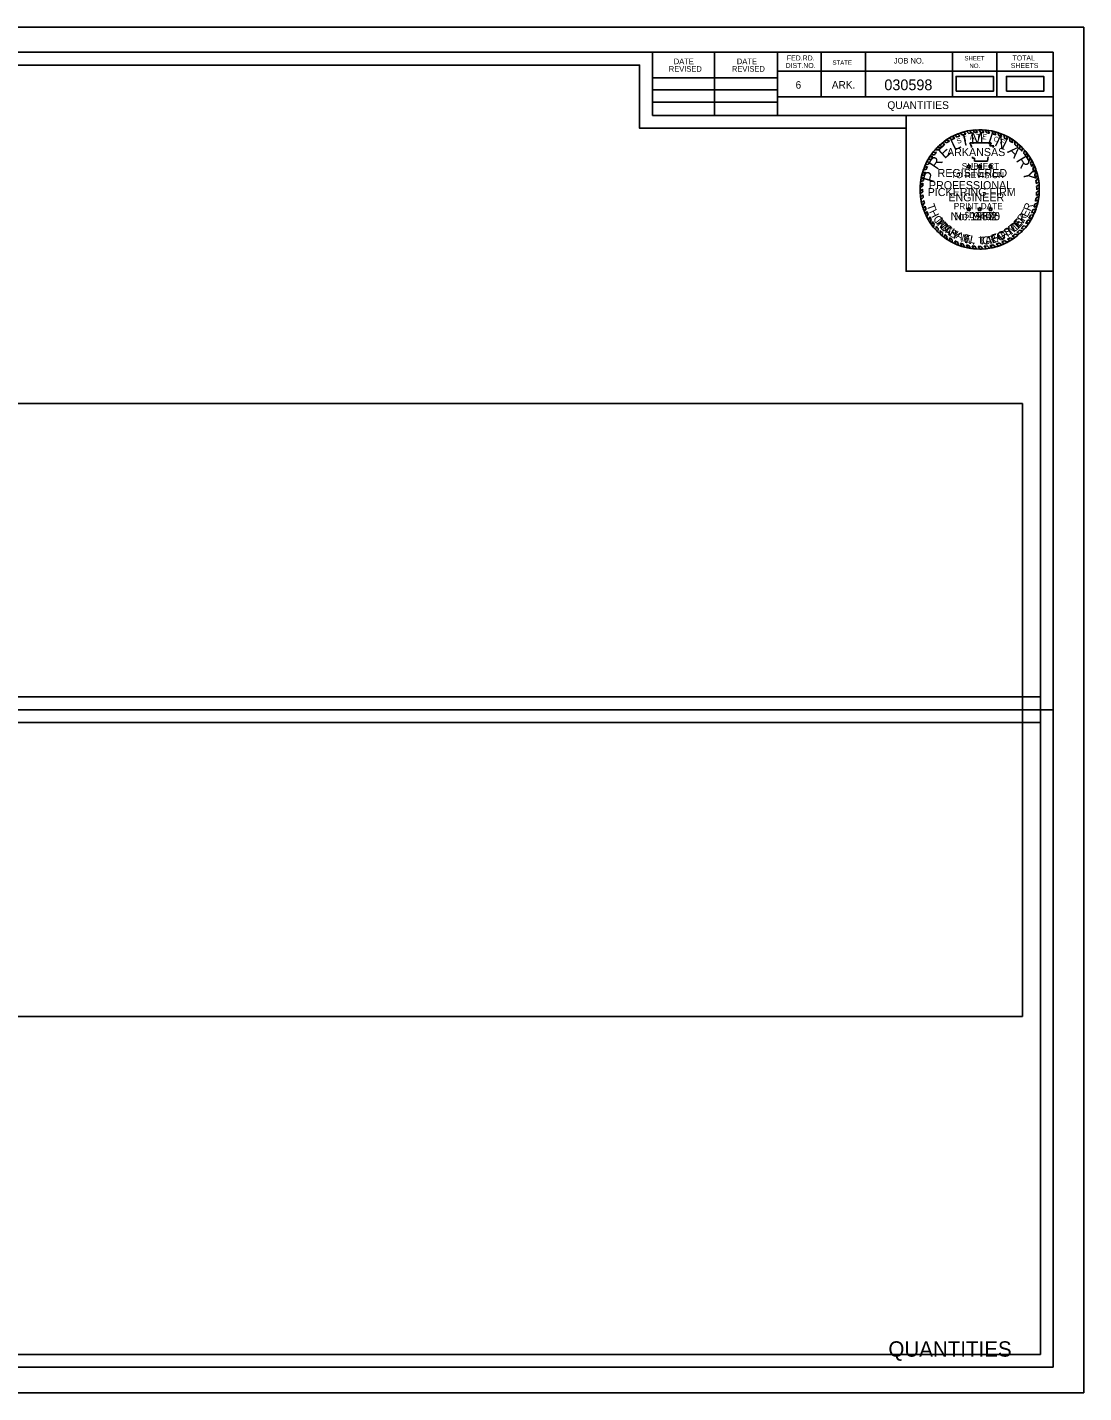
# Model space of a CAD drawing. Extents: x 1369904 to 1372237, y 380119 to 380332.
# Drawn here: x 1371571.9 to 1371736.9, y 380119.1 to 380332.4 of the extents above; entities that cross this region are included whole.
import ezdxf

# ---------------------------------------------------------------- set-up
doc = ezdxf.new("R2010")
doc.units = 0
for name, color, linetype in [('Default', 7, 'Continuous'), ('R_Border', 7, 'Continuous'), ('R_Border Notes', 7, 'Continuous'), ('R_Border Plan-Plan', 7, 'Continuous'), ('R_Border Title', 7, 'Continuous'), ('R_No Plot', 7, 'Continuous'), ('STAMP_PE_CRAFTON', 7, 'Continuous'), ('STAMP_PE_FOSTER', 7, 'Continuous'), ('STAMP_PE_SEAL-INFO', 7, 'Continuous'), ('STAMP_PE_TAEGTMEYER', 7, 'Continuous'), ('STAMP_PE_TXT', 7, 'Continuous'), ('STAMP_PRELIMINARY', 7, 'Continuous')]:
    doc.layers.add(name, color=color, linetype=linetype)

msp = doc.modelspace()

# ---------------------------------------------------------------- linework, layer by layer
at = {"layer": 'Default'}
for points in [[(1371717, 380322.41), (1371722.83, 380322.41), (1371722.83, 380324.72), (1371717, 380324.72)], [(1371724.87, 380322.41), (1371730.7, 380322.41), (1371730.7, 380324.72), (1371724.87, 380324.72)], [(1371420.25, 380177.85), (1371727.35, 380177.85), (1371727.35, 380273.61), (1371420.25, 380273.61)]]:
    msp.add_lwpolyline(points, close=True, dxfattribs=at)
at = {"layer": 'R_Border'}
for p, q in [((1371416, 380328.5), (1371732.18, 380328.5)), ((1371669.54, 380318.62), (1371669.54, 380328.5)), ((1371679.22, 380318.62), (1371679.22, 380328.5)), ((1371689.08, 380328.5), (1371689.08, 380318.62)), ((1371695.92, 380328.5), (1371695.92, 380321.56)), ((1371702.86, 380328.5), (1371702.86, 380321.56)), ((1371716.44, 380328.5), (1371716.44, 380321.56)), ((1371723.38, 380328.5), (1371723.38, 380321.56)), ((1371732.18, 380123.04), (1371732.18, 380328.5)), ((1371732.18, 380325.56), (1371689.08, 380325.56)), ((1371732.18, 380325.58), (1371732.18, 380325.58)), ((1371669.54, 380324.48), (1371689.08, 380324.48)), ((1371669.54, 380322.62), (1371689.08, 380322.62)), ((1371732.18, 380321.56), (1371689.08, 380321.56)), ((1371692.04, 380321.56), (1371732.18, 380321.56)), ((1371669.54, 380320.68), (1371689.08, 380320.68)), ((1371732.18, 380318.62), (1371669.54, 380318.62)), ((1371732.18, 380123.04), (1371416, 380123.04))]:
    msp.add_line(p, q, dxfattribs=at)
at = {"layer": 'R_Border Plan-Plan'}
msp.add_line((1371416, 380225.77), (1371732.18, 380225.77), dxfattribs=at)
at = {"layer": 'R_No Plot'}
for points in [[(1371403.6, 380332.4), (1371736.94, 380332.4), (1371736.94, 380119.06), (1371403.6, 380119.06)], [(1371730.18, 380227.77), (1371418, 380227.77), (1371418, 380326.5), (1371667.54, 380326.5), (1371667.54, 380316.62), (1371685.08, 380316.62), (1371709.18, 380316.62), (1371709.18, 380294.29), (1371730.18, 380294.29)], [(1371418, 380326.5), (1371667.54, 380326.5), (1371667.54, 380316.62), (1371685.08, 380316.62), (1371709.18, 380316.62), (1371709.18, 380294.29), (1371730.18, 380294.29), (1371730.18, 380125.04), (1371418, 380125.04)], [(1371709.18, 380318.62), (1371732.18, 380318.62), (1371732.18, 380294.29), (1371709.18, 380294.29)], [(1371418, 380223.77), (1371730.18, 380223.77), (1371730.18, 380125.04), (1371418, 380125.04)]]:
    msp.add_lwpolyline(points, close=True, dxfattribs=at)
at = {"layer": 'STAMP_PE_SEAL-INFO'}
for p, q in [((1371715.52, 380314.83), (1371715.96, 380314.63)), ((1371715.91, 380315.07), (1371716.34, 380314.85)), ((1371716.36, 380315.33), (1371716.82, 380315.1)), ((1371716.79, 380315.54), (1371717.18, 380315.26)), ((1371717.29, 380315.75), (1371717.59, 380315.43)), ((1371717.64, 380315.88), (1371718.02, 380315.57)), ((1371718.23, 380316.06), (1371718.52, 380315.71)), ((1371718.62, 380316.16), (1371718.98, 380315.82)), ((1371719.1, 380316.26), (1371719.4, 380315.89)), ((1371719.62, 380316.33), (1371719.9, 380315.95)), ((1371720.35, 380315.97), (1371720.04, 380316.37)), ((1371720.85, 380315.98), (1371720.57, 380316.39)), ((1371721.31, 380315.96), (1371721.05, 380316.38)), ((1371721.82, 380315.91), (1371721.52, 380316.35)), ((1371722.24, 380315.84), (1371721.98, 380316.3)), ((1371722.8, 380315.72), (1371722.63, 380316.18)), ((1371723.21, 380315.62), (1371723.05, 380316.09)), ((1371723.66, 380315.47), (1371723.52, 380315.95)), ((1371724.08, 380315.31), (1371723.93, 380315.81)), ((1371724.54, 380315.1), (1371724.43, 380315.6)), ((1371724.98, 380314.87), (1371724.9, 380315.38)), ((1371725.37, 380314.65), (1371725.33, 380315.15)), ((1371725.81, 380314.36), (1371725.77, 380314.88)), ((1371713.38, 380312.86), (1371713.93, 380312.88)), ((1371713.72, 380313.27), (1371714.24, 380313.23)), ((1371714.04, 380313.61), (1371714.59, 380313.57)), ((1371714.38, 380313.94), (1371714.84, 380313.8)), ((1371714.72, 380314.24), (1371715.25, 380314.14)), ((1371715.1, 380314.56), (1371715.56, 380314.36)), ((1371719.16, 380314.36), (1371722.5, 380314.36)), ((1371719.28, 380314.05), (1371719.16, 380314.36)), ((1371719.38, 380313.75), (1371719.28, 380314.05)), ((1371719.39, 380313.64), (1371719.38, 380313.75)), ((1371722.5, 380314.36), (1371722.28, 380313.87)), ((1371722.28, 380313.87), (1371722.91, 380313.87)), ((1371722.91, 380313.87), (1371722.76, 380313.64)), ((1371726.17, 380314.1), (1371726.2, 380314.58)), ((1371726.61, 380313.72), (1371726.63, 380314.25)), ((1371726.92, 380313.43), (1371726.99, 380313.93)), ((1371727.28, 380313.06), (1371727.35, 380313.58)), ((1371727.56, 380312.74), (1371727.69, 380313.21)), ((1371727.88, 380312.32), (1371728.02, 380312.82)), ((1371712.01, 380310.5), (1371712.52, 380310.64)), ((1371712.2, 380310.93), (1371712.7, 380311.03)), ((1371712.39, 380311.32), (1371712.88, 380311.38)), ((1371712.62, 380311.74), (1371713.11, 380311.76)), ((1371712.86, 380312.14), (1371713.38, 380312.18)), ((1371713.1, 380312.49), (1371713.6, 380312.48)), ((1371719.58, 380311.93), (1371719.55, 380312.15)), ((1371719.89, 380311.93), (1371719.58, 380311.93)), ((1371719.89, 380311.5), (1371719.89, 380311.93)), ((1371721.92, 380311.5), (1371719.89, 380311.5)), ((1371721.94, 380311.84), (1371721.92, 380311.5)), ((1371722.02, 380312.15), (1371721.94, 380311.84)), ((1371728.1, 380312.01), (1371728.28, 380312.47)), ((1371728.41, 380311.51), (1371728.59, 380312)), ((1371728.61, 380311.14), (1371728.84, 380311.59)), ((1371728.84, 380310.66), (1371729.07, 380311.15)), ((1371728.98, 380310.32), (1371729.24, 380310.76)), ((1371711.88, 380308.48), (1371711.44, 380308.25)), ((1371711.97, 380308.94), (1371711.5, 380308.69)), ((1371711.6, 380309.18), (1371712.07, 380309.37)), ((1371711.71, 380309.59), (1371712.19, 380309.76)), ((1371711.86, 380310.09), (1371712.35, 380310.23)), ((1371729.18, 380309.77), (1371729.45, 380310.25)), ((1371729.28, 380309.41), (1371729.58, 380309.86)), ((1371729.42, 380308.85), (1371729.73, 380309.3)), ((1371729.49, 380308.47), (1371729.84, 380308.82)), ((1371711.79, 380307.62), (1371711.36, 380307.36)), ((1371711.77, 380307.12), (1371711.36, 380306.79)), ((1371711.78, 380306.72), (1371711.38, 380306.39)), ((1371711.82, 380308.04), (1371711.39, 380307.76)), ((1371729.55, 380307.96), (1371729.92, 380308.3)), ((1371729.55, 380306.11), (1371729.98, 380306.37)), ((1371729.58, 380307.54), (1371729.97, 380307.84)), ((1371729.59, 380306.62), (1371730, 380306.9)), ((1371729.6, 380307.03), (1371730, 380307.35)), ((1371711.81, 380306.22), (1371711.44, 380305.86)), ((1371711.86, 380305.79), (1371711.51, 380305.42)), ((1371711.94, 380305.33), (1371711.6, 380304.96)), ((1371712.03, 380304.91), (1371711.72, 380304.5)), ((1371712.16, 380304.47), (1371711.86, 380304.05)), ((1371729.15, 380304.28), (1371729.64, 380304.48)), ((1371729.3, 380304.77), (1371729.77, 380304.98)), ((1371729.4, 380305.23), (1371729.86, 380305.42)), ((1371729.49, 380305.73), (1371729.94, 380305.95)), ((1371712.3, 380304.04), (1371712.02, 380303.63)), ((1371712.46, 380303.62), (1371712.2, 380303.19)), ((1371712.64, 380303.23), (1371712.41, 380302.77)), ((1371712.87, 380302.77), (1371712.68, 380302.28)), ((1371713.11, 380302.37), (1371712.92, 380301.9)), ((1371713.31, 380302.06), (1371713.2, 380301.51)), ((1371728.2, 380302.27), (1371728.67, 380302.26)), ((1371728.37, 380302.55), (1371728.87, 380302.61)), ((1371728.64, 380303.05), (1371729.13, 380303.12)), ((1371728.8, 380303.39), (1371729.29, 380303.48)), ((1371729.01, 380303.9), (1371729.5, 380304.03)), ((1371713.59, 380301.67), (1371713.49, 380301.14)), ((1371713.89, 380301.29), (1371713.81, 380300.77)), ((1371714.2, 380300.95), (1371714.13, 380300.43)), ((1371714.52, 380300.63), (1371714.49, 380300.1)), ((1371714.86, 380300.32), (1371714.86, 380299.79)), ((1371715.22, 380300.02), (1371715.24, 380299.5)), ((1371726.23, 380300.09), (1371726.7, 380299.95)), ((1371726.5, 380300.32), (1371726.98, 380300.19)), ((1371726.91, 380300.69), (1371727.35, 380300.55)), ((1371727.16, 380300.95), (1371727.64, 380300.86)), ((1371727.55, 380301.38), (1371728.01, 380301.3)), ((1371727.86, 380301.78), (1371728.36, 380301.78)), ((1371715.56, 380299.77), (1371715.6, 380299.25)), ((1371715.99, 380299.49), (1371716.05, 380298.98)), ((1371716.34, 380299.28), (1371716.43, 380298.77)), ((1371716.82, 380299.03), (1371716.98, 380298.51)), ((1371717.19, 380298.87), (1371717.37, 380298.35)), ((1371717.69, 380298.67), (1371717.89, 380298.17)), ((1371718.09, 380298.54), (1371718.32, 380298.05)), ((1371718.6, 380298.4), (1371718.82, 380297.93)), ((1371719, 380298.31), (1371719.25, 380297.86)), ((1371719.5, 380298.23), (1371719.74, 380297.79)), ((1371719.94, 380298.19), (1371720.21, 380297.76)), ((1371720.42, 380298.16), (1371720.72, 380297.74)), ((1371720.88, 380298.16), (1371721.23, 380297.76)), ((1371721.4, 380298.18), (1371721.73, 380297.8)), ((1371721.84, 380298.23), (1371722.21, 380297.87)), ((1371722.28, 380298.3), (1371722.67, 380297.96)), ((1371722.78, 380298.4), (1371723.15, 380298.08)), ((1371723.24, 380298.53), (1371723.65, 380298.23)), ((1371723.73, 380298.69), (1371724.17, 380298.42)), ((1371724.15, 380298.85), (1371724.57, 380298.59)), ((1371724.61, 380299.06), (1371725.09, 380298.85)), ((1371725.01, 380299.28), (1371725.43, 380299.04)), ((1371725.43, 380299.52), (1371725.88, 380299.33)), ((1371725.77, 380299.75), (1371726.21, 380299.56))]:
    msp.add_line(p, q, dxfattribs=at)
for radius, start, end in [(9.32, 123.6199, 126.5906), (9.32, 117.6544, 120.8099), (8.91, 115.6869, 119.1583), (9.32, 111.3124, 114.7026), (8.91, 110.3086, 113.1659), (9.32, 105.2339, 109.0352), (8.91, 104.0352, 107.3615), (9.32, 99.7525, 102.7765), (8.91, 98.258, 101.0329), (9.32, 93.9381, 96.5517), (8.91, 92.1102, 95.0367), (9.32, 87.7298, 90.6707), (8.91, 85.9628, 88.9097), (9.32, 81.9732, 84.8236), (8.91, 79.9264, 82.696), (9.32, 75.3125, 77.9426), (8.91, 73.5575, 76.2314), (9.32, 69.6061, 72.3058), (8.91, 67.6248, 70.504), (9.32, 63.1329, 66.2704), (8.91, 61.1558, 64.3784), (9.32, 56.9003, 60.0942), (9.32, 141.6056, 144.4486), (8.91, 139.301, 142.5873), (9.32, 135.4021, 138.3031), (8.91, 133.1331, 136.2562), (9.32, 129.7326, 132.5376), (8.91, 127.5297, 130.9683), (8.91, 121.9746, 125.11), (8.91, 54.9238, 58.2702), (8.91, 48.3016, 52.0395), (9.32, 50.3492, 53.7159), (8.91, 42.2212, 45.5512), (9.32, 44.3405, 47.3929), (8.91, 36.135, 39.5311), (9.32, 38.1247, 41.2316), (9.32, 152.864, 155.5189), (8.91, 156.3402, 159.2319), (9.32, 147.0072, 149.899), (8.91, 151.0315, 153.573), (8.91, 145.0197, 148.2104), (8.91, 29.9032, 33.6645), (9.32, 31.9614, 35.4294), (8.91, 23.7732, 27.2211), (9.32, 25.9391, 29.0125), (9.32, 19.9538, 23.3141), (9.32, 170.0003, 172.6878), (9.32, 164.3068, 166.894), (9.32, 158.4077, 161.0701), (8.91, 167.9048, 170.9039), (8.91, 162.4331, 165.0013), (8.91, 17.6802, 21.4251), (8.91, 11.5444, 15.2364), (8.91, 5.7599, 9.0606), (9.32, 13.8421, 17.4447), (9.32, 7.5852, 10.8621), (9.32, 175.7409, 178.2066), (9.32, 181.7251, 184.1626), (8.91, 179.6454, 182.2633), (8.91, 173.73, 176.4734), (8.91, 353.8632, 357.1274), (8.91, 359.7329, 3.0639), (9.32, 1.7215, 4.7268), (9.32, 355.7156, 358.9569), (9.32, 187.4204, 190.1927), (9.32, 193.0369, 195.9973), (8.91, 185.4539, 188.234), (8.91, 191.2274, 193.9858), (8.91, 196.9675, 199.8353), (8.91, 341.777, 345.0925), (8.91, 348.0778, 351.3435), (9.32, 343.8925, 347.035), (9.32, 349.8305, 353.0885), (9.32, 198.8967, 201.6281), (9.32, 204.5479, 207.4328), (8.91, 202.7761, 205.4791), (9.32, 210.8636, 213.6571), (8.91, 208.7883, 211.7934), (8.91, 214.1838, 217.2747), (8.91, 323.5851, 327.4407), (9.32, 325.4405, 328.9872), (8.91, 329.5549, 333.2076), (8.91, 335.6038, 339.1858), (9.32, 331.4037, 334.9332), (9.32, 337.3837, 340.9933), (9.32, 216.6115, 219.491), (9.32, 222.48, 225.3801), (8.91, 220.3909, 223.3056), (9.32, 228.3665, 231.348), (8.91, 226.2494, 229.2407), (8.91, 232.229, 234.9336), (8.91, 304.823, 308.5143), (9.32, 306.3721, 310.208), (8.91, 310.7744, 314.3161), (9.32, 312.4518, 315.6633), (8.91, 316.6531, 320.3711), (9.32, 318.2846, 321.8043), (9.32, 234.295, 236.9452), (8.91, 238.2223, 240.8353), (9.32, 240.1977, 242.8613), (8.91, 244.3204, 246.9486), (9.32, 246.576, 249.1558), (8.91, 250.3491, 253.1216), (9.32, 252.5967, 255.3252), (8.91, 256.505, 259.1192), (9.32, 258.4433, 261.1398), (8.91, 262.3783, 265.2012), (9.32, 264.1978, 267.1009), (8.91, 268.3215, 271.277), (9.32, 270.2548, 273.3361), (8.91, 274.6157, 277.4486), (9.32, 276.4239, 279.4357), (8.91, 280.3459, 283.5814), (9.32, 282.3199, 285.3702), (8.91, 286.6423, 289.9783), (9.32, 288.5709, 291.9733), (8.91, 292.8745, 296.1185), (9.32, 294.6481, 298.2166), (8.91, 299.0768, 302.1724), (9.32, 300.621, 303.8703)]:
    msp.add_arc((1371720.68, 380307.07), radius, start, end, dxfattribs=at)
at = {"layer": 'STAMP_PE_TXT'}
for p, q in [((1371718.86, 380310.64), (1371718.66, 380310.78)), ((1371718.66, 380310.78), (1371718.91, 380310.78)), ((1371718.79, 380310.41), (1371718.86, 380310.64)), ((1371718.98, 380310.55), (1371718.79, 380310.41)), ((1371718.91, 380310.78), (1371718.98, 380311.02)), ((1371718.98, 380311.02), (1371719.06, 380310.78)), ((1371719.18, 380310.41), (1371718.98, 380310.55)), ((1371719.06, 380310.78), (1371719.31, 380310.78)), ((1371719.31, 380310.78), (1371719.11, 380310.64)), ((1371719.11, 380310.64), (1371719.18, 380310.41)), ((1371720.56, 380310.64), (1371720.36, 380310.78)), ((1371720.36, 380310.78), (1371720.61, 380310.78)), ((1371720.48, 380310.41), (1371720.56, 380310.64)), ((1371720.68, 380310.55), (1371720.48, 380310.41)), ((1371720.61, 380310.78), (1371720.68, 380311.02)), ((1371720.68, 380311.02), (1371720.76, 380310.78)), ((1371720.88, 380310.41), (1371720.68, 380310.55)), ((1371720.76, 380310.78), (1371721, 380310.78)), ((1371721, 380310.78), (1371720.81, 380310.64)), ((1371720.81, 380310.64), (1371720.88, 380310.41)), ((1371722.26, 380310.64), (1371722.06, 380310.78)), ((1371722.06, 380310.78), (1371722.31, 380310.78)), ((1371722.18, 380310.41), (1371722.26, 380310.64)), ((1371722.38, 380310.55), (1371722.18, 380310.41)), ((1371722.31, 380310.78), (1371722.38, 380311.02)), ((1371722.38, 380311.02), (1371722.46, 380310.78)), ((1371722.58, 380310.41), (1371722.38, 380310.55)), ((1371722.46, 380310.78), (1371722.7, 380310.78)), ((1371722.7, 380310.78), (1371722.5, 380310.64)), ((1371722.5, 380310.64), (1371722.58, 380310.41)), ((1371718.91, 380304.08), (1371718.98, 380304.31)), ((1371718.98, 380304.31), (1371719.06, 380304.08)), ((1371720.61, 380304.08), (1371720.68, 380304.31)), ((1371720.68, 380304.31), (1371720.76, 380304.08)), ((1371722.31, 380304.08), (1371722.38, 380304.31)), ((1371722.38, 380304.31), (1371722.46, 380304.08)), ((1371718.86, 380303.93), (1371718.66, 380304.08)), ((1371718.66, 380304.08), (1371718.91, 380304.08)), ((1371718.79, 380303.7), (1371718.86, 380303.93)), ((1371718.98, 380303.84), (1371718.79, 380303.7)), ((1371719.18, 380303.7), (1371718.98, 380303.84)), ((1371719.06, 380304.08), (1371719.31, 380304.08)), ((1371719.31, 380304.08), (1371719.11, 380303.93)), ((1371719.11, 380303.93), (1371719.18, 380303.7)), ((1371720.56, 380303.93), (1371720.36, 380304.08)), ((1371720.36, 380304.08), (1371720.61, 380304.08)), ((1371720.48, 380303.7), (1371720.56, 380303.93)), ((1371720.68, 380303.84), (1371720.48, 380303.7)), ((1371720.88, 380303.7), (1371720.68, 380303.84)), ((1371720.76, 380304.08), (1371721, 380304.08)), ((1371721, 380304.08), (1371720.81, 380303.93)), ((1371720.81, 380303.93), (1371720.88, 380303.7)), ((1371722.26, 380303.93), (1371722.06, 380304.08)), ((1371722.06, 380304.08), (1371722.31, 380304.08)), ((1371722.18, 380303.7), (1371722.26, 380303.93)), ((1371722.38, 380303.84), (1371722.18, 380303.7)), ((1371722.58, 380303.7), (1371722.38, 380303.84)), ((1371722.46, 380304.08), (1371722.7, 380304.08)), ((1371722.7, 380304.08), (1371722.5, 380303.93)), ((1371722.5, 380303.93), (1371722.58, 380303.7))]:
    msp.add_line(p, q, dxfattribs=at)
at = {"layer": 'STAMP_PRELIMINARY'}
msp.add_circle((1371720.68, 380307.07), 9.32, dxfattribs=at)

# ---------------------------------------------------------------- texts
at = {"layer": 'R_Border'}
for s, height, p in [('FED.RD.', 0.782, (1371690.56, 380327.22)), ('JOB NO.', 0.879, (1371707.26, 380326.74)), ('SHEET', 0.684, (1371718.3, 380327.22)), ('TOTAL', 0.782, (1371725.82, 380327.22)), ('REVISED', 0.879, (1371672.1, 380325.46)), ('DATE', 0.879, (1371672.88, 380326.64)), ('REVISED', 0.879, (1371681.96, 380325.46)), ('DATE', 0.879, (1371682.74, 380326.64)), ('DIST.NO.', 0.782, (1371690.36, 380326.04)), ('STATE', 0.684, (1371697.68, 380326.54)), ('NO.', 0.684, (1371719.08, 380326.04)), ('SHEETS', 0.782, (1371725.54, 380326.04)), ('6', 1.17, (1371691.92, 380322.82)), ('ARK.', 1.172, (1371697.58, 380322.82))]:
    msp.add_text(s, height=height, dxfattribs=at).set_placement(p)
at = {"layer": 'R_Border Notes'}
for s, height, p in [('030598', 1.68, (1371705.79, 380322.57)), ('QUANTITIES', 1.2, (1371706.25, 380319.64))]:
    msp.add_text(s, height=height, dxfattribs=at).set_placement(p)
at = {"layer": 'R_Border Title'}
msp.add_text('QUANTITIES', height=2.4, dxfattribs=at).set_placement((1371706.42, 380124.69))
at = {"layer": 'STAMP_PE_CRAFTON'}
for s, rotation, p in [('T', 310.7442, (1371713.65, 380301.97)), ('N', 49.2411, (1371726.97, 380301.09)), ('O', 317.6422, (1371714.32, 380301.15)), ('N', 324.4537, (1371715.16, 380300.37)), ('Y', 331.1686, (1371716.19, 380299.65)), ('N', 347.4752, (1371718.25, 380298.74)), ('R', 14.8189, (1371722.25, 380298.52)), ('A', 20.5125, (1371723.36, 380298.82)), ('F', 28.7821, (1371724.34, 380299.2)), ('T', 34.1136, (1371725.26, 380299.71)), ('O', 41.8391, (1371726.12, 380300.31)), ('.', 356.8926, (1371719.48, 380298.46)), ('C', 6.0117, (1371721.15, 380298.41))]:
    msp.add_text(s, height=1.25, rotation=rotation, dxfattribs=at).set_placement(p)
msp.add_text('No. 12370', height=1.25, dxfattribs=at).set_placement((1371716.14, 380302.26))
at = {"layer": 'STAMP_PE_FOSTER'}
for s, rotation, p in [('M', 308.339, (1371713.8, 380302.09)), ('E', 46.9613, (1371726.68, 380301.06)), ('R', 54.5031, (1371727.41, 380301.88)), ('I', 314.1842, (1371714.6, 380301.15)), ('C', 319.8733, (1371714.95, 380300.8)), ('H', 327.7235, (1371715.88, 380300.06)), ('A', 335.7276, (1371716.86, 380299.48)), ('E', 343.5779, (1371718, 380299.01)), ('L', 350.8115, (1371719.06, 380298.73)), ('F', 15.8691, (1371722.72, 380298.82)), ('O', 23.719, (1371723.76, 380299.15)), ('S', 31.7234, (1371724.87, 380299.68)), ('T', 39.4194, (1371725.83, 380300.31)), ('L', 1.2666, (1371720.6, 380298.58)), ('.', 6.8035, (1371721.64, 380298.63))]:
    msp.add_text(s, height=1.2, rotation=rotation, dxfattribs=at).set_placement(p)
msp.add_text('No. 9402', height=1.25, dxfattribs=at).set_placement((1371716.67, 380302.26))
at = {"layer": 'STAMP_PE_TAEGTMEYER'}
for s, rotation, p in [('T', 289.646, (1371712.38, 380304.58)), ('R', 69.57, (1371728.63, 380303.58)), ('H', 296.7339, (1371712.74, 380303.59)), ('O', 303.7708, (1371713.33, 380302.49)), ('M', 314.2033, (1371713.98, 380301.53)), ('E', 46.8094, (1371726.72, 380300.84)), ('Y', 53.9986, (1371727.46, 380301.66)), ('E', 63.0984, (1371728.13, 380302.6)), ('A', 321.0594, (1371714.95, 380300.57)), ('S', 327.8239, (1371715.77, 380299.93)), ('N', 344.2727, (1371717.67, 380298.92)), ('E', 17.6836, (1371722.63, 380298.6)), ('G', 23.3052, (1371723.68, 380298.93)), ('T', 31.466, (1371724.78, 380299.42)), ('M', 39.3, (1371725.68, 380299.97)), ('.', 350.6464, (1371718.88, 380298.59)), ('T', 3.0061, (1371720.55, 380298.39)), ('A', 8.9826, (1371721.59, 380298.44))]:
    msp.add_text(s, height=1.25, rotation=rotation, dxfattribs=at).set_placement(p)
msp.add_text('No. 19605', height=1.25, dxfattribs=at).set_placement((1371716.14, 380302.26))
at = {"layer": 'STAMP_PE_TXT'}
for s, rotation, p in [('S', 23.5541, (1371717.28, 380314.17)), ('T', 16.311, (1371718.2, 380314.54)), ('A', 9.0679, (1371719.17, 380314.8)), ('T', 1.8248, (1371720.15, 380314.93)), ('E', 355.2002, (1371721.06, 380314.93)), ('O', 342.2506, (1371722.79, 380314.66)), ('F', 335.0075, (1371723.76, 380314.32))]:
    msp.add_text(s, height=0.781, rotation=rotation, dxfattribs=at).set_placement(p)
for s, p in [('ARKANSAS', (1371715.58, 380312.28)), ('REGISTERED', (1371714.1, 380309.01)), ('PROFESSIONAL', (1371712.75, 380307.11)), ('ENGINEER', (1371715.79, 380305.21))]:
    msp.add_text(s, height=1.25, dxfattribs=at).set_placement(p)
at = {"layer": 'STAMP_PRELIMINARY'}
for s, rotation, p in [('L', 25.513, (1371716.69, 380313.09)), ('I', 12.5248, (1371718.22, 380313.85)), ('M', 3.1074, (1371719.32, 380314.16)), ('I', 342.3164, (1371721.79, 380314.23)), ('N', 333.9382, (1371722.89, 380313.96)), ('E', 42.3578, (1371715.21, 380311.76)), ('A', 315.6579, (1371724.93, 380312.93)), ('R', 56.2292, (1371714.05, 380310.03)), ('R', 301.3831, (1371726.3, 380311.62)), ('P', 73.913, (1371713.5, 380308.01)), ('Y', 283.2593, (1371727.38, 380309.83))]:
    msp.add_text(s, height=1.8, rotation=rotation, dxfattribs=at).set_placement(p)
for s, height, p in [('SUBJECT', 0.96, (1371717.88, 380310.22)), ('TO REVISION', 0.96, (1371716.22, 380308.83)), ('PICKERING FIRM', 1.25, (1371712.56, 380306.03)), ('PRINT DATE', 0.96, (1371716.64, 380303.98)), ('$DATE$', 0.96, (1371718.32, 380302.6))]:
    msp.add_text(s, height=height, dxfattribs=at).set_placement(p)

doc.saveas('drawing.dxf')
